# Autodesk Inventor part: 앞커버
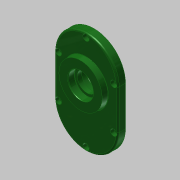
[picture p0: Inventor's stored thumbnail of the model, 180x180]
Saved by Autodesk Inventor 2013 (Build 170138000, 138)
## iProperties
Created: 2016-12
Part Number: 앞커버
Material: 알루미늄 6061
Document SubType Name: Modeling
Designer: mduedu
Density: 2.71 g/cm^3
Mass: 264.666 g
Surface Area: 264.413 cm^2
Volume: 97.6629 cm^3
Author: mduedu
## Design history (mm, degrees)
sketch "스케치1"
  geometry: L1 (40, -25)-(40, 25); L2 (-40, 25)-(-40, -25); L3 (-40, -25)-(40, 25); L4 (40, -25)-(-40, 25); A1 r 40 centre (0, 25) between (40, 25) and (-40, 25); A2 r 40 centre (0, -25) between (-40, -25) and (40, -25); 1 further point
  constraints: 8 end point, 4 point on circle, 4 tangent, 2 centre point, 2 midpoint, 1 parallel, 1 vertical
  dimensions: "d0" = 130 dimension on A2 A1; "d2" = 80 distance between parallel lines of L1 L2
extrude "돌출1" new body sketch "스케치1" distance "d3" = 10; taper "d4" = 0 deg
sketch "스케치2"
  geometry: C1 r 21 at (0, 11); 1 further point
  constraints: 1 centre point, 1 vertical alignment
  dimensions: "d5" = 42 diameter of C1; "d7" = 11 distance of C1.centre point (0, 0)
extrude "돌출2" join sketch "스케치2" distance "d8" = 7; taper "d9" = 0 deg
sketch "스케치3"
  geometry: C1 r 15 at (0, -33.1); C2 r 21 at (0, 11) reference; 1 further point
  constraints: 1 centre point, 1 vertical alignment
  dimensions: "d10" = 30 diameter of C1; "d71" = 44.1 distance of C1.centre C2.centre
extrude "돌출3" join sketch "스케치3" distance "d12" = 7; taper "d13" = 0 deg
sketch "스케치4"
  geometry: C1 r 28 at (0, 11); A1 r 21 centre (0, 11) between (8.978, -7.984) and (-8.978, -7.984) reference; 1 further point
  constraints: 1 centre point, 1 coincident
  dimensions: "d14" = 56 diameter of C1
extrude "돌출4" join sketch "스케치4" distance "d15" = 7; taper "d16" = -5 deg
hole "구멍1" diameter "d19" = 35; stored, may be unused: countersink angle "d23" = 90 deg, drill point angle "d25" = 0 deg; dims "d17" = 10, "d18" = 10, "d20" = 6, "d21" = 4, "d22" = 2, "d24" = 10
hole "구멍2" diameter "d28" = 22; stored, may be unused: countersink angle "d32" = 90 deg, drill point angle "d34" = 0 deg; dims "d26" = 10, "d27" = 10, "d29" = 6, "d30" = 4, "d31" = 2, "d33" = 7
hole "구멍3" diameter "d37" = 19; stored, may be unused: countersink angle "d41" = 90 deg, drill point angle "d43" = 0 deg; dims "d35" = 10, "d36" = 10, "d38" = 6, "d39" = 4, "d40" = 2, "d42" = 1
hole "구멍4" diameter "d46" = 32; stored, may be unused: countersink angle "d50" = 90 deg, drill point angle "d52" = 0 deg; dims "d47" = 6, "d48" = 4, "d49" = 2, "d51" = 8.3, "d89" = 10, "d90" = 10
hole "구멍5" diameter "d55" = 25; stored, may be unused: countersink angle "d59" = 90 deg, drill point angle "d61" = 0 deg; dims "d53" = 10, "d54" = 10, "d56" = 6, "d57" = 4, "d58" = 2, "d60" = 8
fillet "모깎기1" dims "d62" = 0.3
fillet "모깎기2" dims "d63" = 2
chamfer "모따기1" distance "d64" = 1; stored, may be unused: second distance "d65" = 2, angle "d66" = 45 deg
chamfer "모따기2" distance "d91" = 0.8; stored, may be unused: second distance "d92" = 2, angle "d93" = 30 deg
fillet "모깎기4" dims "d68" = 2
fillet "모깎기5" dims "d69" = 0.3
fillet "모깎기6" dims "d70" = 2
sketch "스케치5"
  geometry: L1 (-40, 25)-(-40, -25) reference; L2 (40, -25)-(40, 25) reference; L3 (35, 25)-(35, -25); L4 (-35, -25)-(-35, 25); A1 r 40 centre (0, 25) between (40, 25) and (-40, 25) reference; A2 r 40 centre (0, -25) between (-40, -25) and (40, -25) reference; A3 r 35 centre (0, 25) between (35, 25) and (-35, 25); A4 r 35 centre (0, -25) between (-35, -25) and (35, -25); 2 further points
  constraints: 5 point on circle, 4 end point, 2 centre point, 1 vertical alignment, 3 other
  dimensions: "d72" = 5 distance between parallel lines of L2 L3
sketch "스케치7"
  geometry: 1 further point
  constraints: 1 other
hole "구멍7" sketch "스케치7" at (0, 60) diameter "d80" = 4.5; stored, may be unused: countersink angle "d84" = 90 deg, drill point angle "d86" = 0 deg; dims "d81" = 6, "d82" = 8, "d83" = 4.6, "d85" = 8
node "솔리드1"
pattern_linear "직사각형 패턴1"
